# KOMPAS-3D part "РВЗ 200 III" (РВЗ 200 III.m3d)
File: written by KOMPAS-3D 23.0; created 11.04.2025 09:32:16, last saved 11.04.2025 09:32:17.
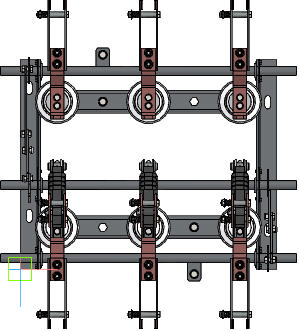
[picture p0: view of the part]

Document properties: Автор: pc; Полное имя файла: C:\Users\pc\Desktop\работа\РВЗ\3D макеты\РВЗ 200 III.m3d

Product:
- Body: Тело 1
    Масса: 0.01131
- Body: Тело 2
    Масса: 0.01131
- Body: Тело 3
    Масса: 0.01131
- Body: Тело 4
    Масса: 1.60238
- Body: Тело 5
    Масса: 1.60238
- Body: Тело 6
    Масса: 0.011176
- Body: Тело 7
    Масса: 0.011176
- Body: Тело 8
    Масса: 0.011176
- Body: Тело 9
    Масса: 0.011176
- Body: Тело 10
    Масса: 0.052628
- Body: Тело 11
    Масса: 0.052628
- Body: Тело 12
    Масса: 1.60238
- Part/product: РВЗ 200 III
    Масса: 4.991028

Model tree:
1. Операция без истории:1
2. Операция без истории:2
3. Операция без истории:3
4. Операция без истории:4
5. Операция без истории:5
6. Операция без истории:6
7. Операция без истории:7
8. Операция без истории:8
9. Операция без истории:9
10. Операция без истории:10
11. Операция без истории:11
12. Операция без истории:12
13. Поверхность без истории:1
14. Поверхность без истории:2
15. Поверхность без истории:3
16. Поверхность без истории:4
17. Поверхность без истории:5
18. Поверхность без истории:6
19. Поверхность без истории:7
20. Поверхность без истории:8
21. Поверхность без истории:9
22. Поверхность без истории:10
23. Поверхность без истории:11
24. Поверхность без истории:12
25. Поверхность без истории:13
26. Поверхность без истории:14
27. Поверхность без истории:15
28. Поверхность без истории:16
29. Поверхность без истории:17
30. Поверхность без истории:18
31. Поверхность без истории:19
32. Поверхность без истории:20
33. Поверхность без истории:21
34. Поверхность без истории:22
35. Поверхность без истории:23
36. Поверхность без истории:24
37. Поверхность без истории:25
38. Поверхность без истории:26
39. Поверхность без истории:27
40. Поверхность без истории:28
41. Поверхность без истории:29
42. Поверхность без истории:30
43. Поверхность без истории:31
44. Поверхность без истории:32
45. Поверхность без истории:33
46. Поверхность без истории:34
47. Поверхность без истории:35
48. Поверхность без истории:36
49. Поверхность без истории:37
50. Поверхность без истории:38
51. Поверхность без истории:39
52. Поверхность без истории:40
53. Поверхность без истории:41
54. Поверхность без истории:42
55. Поверхность без истории:43
56. Поверхность без истории:44
57. Поверхность без истории:45
58. Поверхность без истории:46
59. Поверхность без истории:47
60. Поверхность без истории:48
61. Поверхность без истории:49
62. Поверхность без истории:50
63. Поверхность без истории:51
64. Поверхность без истории:52
65. Поверхность без истории:53
66. Поверхность без истории:54
67. Поверхность без истории:55
68. Поверхность без истории:56
69. Поверхность без истории:57
70. Поверхность без истории:58
71. Поверхность без истории:59
72. Поверхность без истории:60
73. Поверхность без истории:61
74. Поверхность без истории:62
75. Поверхность без истории:63
76. Поверхность без истории:64
77. Поверхность без истории:65
78. Поверхность без истории:66
79. Поверхность без истории:67
80. Поверхность без истории:68
81. Поверхность без истории:69
82. Поверхность без истории:70
83. Поверхность без истории:71
84. Поверхность без истории:72
85. Поверхность без истории:73
86. Поверхность без истории:74
87. Поверхность без истории:75
88. Поверхность без истории:76
89. Поверхность без истории:77
90. Поверхность без истории:78
91. Поверхность без истории:79
92. Поверхность без истории:80
93. Поверхность без истории:81
94. Поверхность без истории:82
95. Поверхность без истории:83
96. Поверхность без истории:84
97. Поверхность без истории:85
98. Поверхность без истории:86
99. Поверхность без истории:87
100. Поверхность без истории:88
101. Поверхность без истории:89
102. Поверхность без истории:90
103. Поверхность без истории:91
104. Поверхность без истории:92
105. Поверхность без истории:93
106. Поверхность без истории:94
107. Поверхность без истории:95
108. Поверхность без истории:96
109. Поверхность без истории:97
110. Поверхность без истории:98
111. Поверхность без истории:99
112. Поверхность без истории:100
113. Поверхность без истории:101
114. Поверхность без истории:102
115. Поверхность без истории:103
116. Поверхность без истории:104
117. Поверхность без истории:105
118. Поверхность без истории:106
119. Поверхность без истории:107
120. Поверхность без истории:108
121. Поверхность без истории:109
122. Поверхность без истории:110
123. Поверхность без истории:111
124. Поверхность без истории:112
125. Поверхность без истории:113
126. Поверхность без истории:114
127. Поверхность без истории:115
128. Поверхность без истории:116
129. Поверхность без истории:117
130. Поверхность без истории:118
131. Поверхность без истории:119
132. Поверхность без истории:120
133. Поверхность без истории:121
134. Поверхность без истории:122
135. Поверхность без истории:123
136. Поверхность без истории:124
137. Поверхность без истории:125
138. Поверхность без истории:126
139. Поверхность без истории:127
140. Поверхность без истории:128
141. Поверхность без истории:129
142. Поверхность без истории:130
143. Поверхность без истории:131
144. Поверхность без истории:132
145. Поверхность без истории:133
146. Поверхность без истории:134
147. Поверхность без истории:135
148. Поверхность без истории:136
149. Поверхность без истории:137
150. Поверхность без истории:138
151. Поверхность без истории:139
152. Поверхность без истории:140
153. Поверхность без истории:141
154. Поверхность без истории:142
155. Поверхность без истории:143
156. Поверхность без истории:144
157. Поверхность без истории:145
158. Поверхность без истории:146
159. Поверхность без истории:147
160. Поверхность без истории:148
161. Поверхность без истории:149
162. Поверхность без истории:150
163. Поверхность без истории:151
164. Поверхность без истории:152
165. Поверхность без истории:153
166. Поверхность без истории:154
167. Поверхность без истории:155
168. Поверхность без истории:156
169. Поверхность без истории:157
170. Поверхность без истории:158
171. Поверхность без истории:159
172. Поверхность без истории:160
173. Поверхность без истории:161
174. Поверхность без истории:162
175. Поверхность без истории:163
176. Поверхность без истории:164
177. Поверхность без истории:165
178. Поверхность без истории:166
179. Поверхность без истории:167
180. Поверхность без истории:168
181. Поверхность без истории:169
182. Поверхность без истории:170
183. Поверхность без истории:171
184. Поверхность без истории:172
185. Поверхность без истории:173
186. Поверхность без истории:174
187. Поверхность без истории:175
188. Поверхность без истории:176
189. Поверхность без истории:177
190. Поверхность без истории:178
191. Поверхность без истории:179
192. Поверхность без истории:180
193. Поверхность без истории:181
194. Поверхность без истории:182
195. Поверхность без истории:183
196. Поверхность без истории:184
197. Поверхность без истории:185
198. Поверхность без истории:186
199. Поверхность без истории:187
200. Поверхность без истории:188
201. Поверхность без истории:189
202. Поверхность без истории:190
203. Поверхность без истории:191
204. Поверхность без истории:192
205. Поверхность без истории:193
206. Поверхность без истории:194
207. Поверхность без истории:195
208. Поверхность без истории:196
209. Поверхность без истории:197
210. Поверхность без истории:198
211. Поверхность без истории:199
212. Поверхность без истории:200
213. Поверхность без истории:201
214. Поверхность без истории:202
215. Поверхность без истории:203
216. Поверхность без истории:204
217. Поверхность без истории:205
218. Поверхность без истории:206
219. Поверхность без истории:207
220. Поверхность без истории:208
221. Поверхность без истории:209
222. Поверхность без истории:210
223. Поверхность без истории:211
224. Поверхность без истории:212
225. Поверхность без истории:213
226. Поверхность без истории:214
227. Поверхность без истории:215
228. Поверхность без истории:216
229. Поверхность без истории:217
230. Поверхность без истории:218
231. Поверхность без истории:219
232. Поверхность без истории:220
233. Поверхность без истории:221
234. Поверхность без истории:222
235. Поверхность без истории:223
236. Поверхность без истории:224
237. Поверхность без истории:225
238. Поверхность без истории:226
239. Поверхность без истории:227
240. Поверхность без истории:228
241. Поверхность без истории:229
242. Поверхность без истории:230
243. Поверхность без истории:231
244. Поверхность без истории:232
245. Поверхность без истории:233
246. Поверхность без истории:234
247. Поверхность без истории:235
248. Поверхность без истории:236
249. Поверхность без истории:237
250. Поверхность без истории:238
251. Поверхность без истории:239
252. Поверхность без истории:240
253. Поверхность без истории:241
254. Поверхность без истории:242
255. Поверхность без истории:243
256. Поверхность без истории:244
257. Поверхность без истории:245
258. Поверхность без истории:246
259. Поверхность без истории:247
260. Поверхность без истории:248
261. Поверхность без истории:249
262. Поверхность без истории:250
263. Поверхность без истории:251
264. Поверхность без истории:252
265. Поверхность без истории:253
266. Поверхность без истории:254
267. Поверхность без истории:255
268. Поверхность без истории:256
269. Поверхность без истории:257
270. Поверхность без истории:258
271. Поверхность без истории:259
272. Поверхность без истории:260
273. Поверхность без истории:261
274. Поверхность без истории:262
275. Поверхность без истории:263
276. Поверхность без истории:264
277. Поверхность без истории:265
278. Поверхность без истории:266
279. Поверхность без истории:267
280. Поверхность без истории:268
281. Поверхность без истории:269
282. Поверхность без истории:270
283. Поверхность без истории:271
284. Поверхность без истории:272
285. Поверхность без истории:273
286. Поверхность без истории:274
287. Поверхность без истории:275
288. Поверхность без истории:276
289. Поверхность без истории:277
290. Поверхность без истории:278
291. Поверхность без истории:279
292. Поверхность без истории:280
293. Поверхность без истории:281
294. Поверхность без истории:282
295. Поверхность без истории:283
296. Поверхность без истории:284
297. Поверхность без истории:285
298. Поверхность без истории:286
299. Поверхность без истории:287
300. Поверхность без истории:288
301. Поверхность без истории:289
302. Поверхность без истории:290
303. Поверхность без истории:291
304. Поверхность без истории:292
305. Поверхность без истории:293
306. Поверхность без истории:294
307. Поверхность без истории:295
308. Поверхность без истории:296
309. Поверхность без истории:297
310. Поверхность без истории:298
311. Поверхность без истории:299
312. Поверхность без истории:300
313. Поверхность без истории:301
314. Поверхность без истории:302
315. Поверхность без истории:303
316. Поверхность без истории:304
317. Поверхность без истории:305
318. Поверхность без истории:306
319. Поверхность без истории:307
320. Поверхность без истории:308
321. Поверхность без истории:309
322. Поверхность без истории:310
323. Поверхность без истории:311
324. Поверхность без истории:312
325. Поверхность без истории:313
326. Поверхность без истории:314
327. Поверхность без истории:315
328. Поверхность без истории:316
329. Поверхность без истории:317
330. Поверхность без истории:318
331. Поверхность без истории:319
332. Поверхность без истории:320
333. Поверхность без истории:321
334. Поверхность без истории:322
335. Поверхность без истории:323
336. Поверхность без истории:324
337. Поверхность без истории:325
338. Поверхность без истории:326
339. Поверхность без истории:327
340. Поверхность без истории:328
341. Поверхность без истории:329
342. Поверхность без истории:330
343. Поверхность без истории:331
344. Поверхность без истории:332
345. Поверхность без истории:333
346. Поверхность без истории:334
347. Поверхность без истории:335
348. Поверхность без истории:336
349. Поверхность без истории:337
350. Поверхность без истории:338
351. Поверхность без истории:339
352. Поверхность без истории:340
353. Поверхность без истории:341
354. Поверхность без истории:342
355. Поверхность без истории:343
356. Поверхность без истории:344
357. Поверхность без истории:345
358. Поверхность без истории:346
359. Поверхность без истории:347
360. Поверхность без истории:348
361. Поверхность без истории:349
362. Поверхность без истории:350
363. Поверхность без истории:351
364. Поверхность без истории:352
365. Поверхность без истории:353
366. Поверхность без истории:354
367. Поверхность без истории:355
368. Поверхность без истории:356
369. Поверхность без истории:357
370. Поверхность без истории:358
371. Поверхность без истории:359
372. Поверхность без истории:360
373. Поверхность без истории:361
374. Поверхность без истории:362
375. Поверхность без истории:363
376. Поверхность без истории:364
377. Поверхность без истории:365
378. Поверхность без истории:366
379. Поверхность без истории:367
380. Поверхность без истории:368
381. Поверхность без истории:369
382. Поверхность без истории:370
383. Поверхность без истории:371
384. Поверхность без истории:372
385. Поверхность без истории:373
386. Поверхность без истории:374
387. Поверхность без истории:375
388. Поверхность без истории:376
389. Поверхность без истории:377
390. Поверхность без истории:378
391. Поверхность без истории:379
